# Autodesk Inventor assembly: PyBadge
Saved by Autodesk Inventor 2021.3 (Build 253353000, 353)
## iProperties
Created: 2021-11
Part Number: PyBadge
Document SubType Name: Assembly
Designer: Administrator
Title: PyBadge v1
Author: Administrator
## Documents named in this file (2)
- c:\worker\convert-fusion-r08\tmp\job-1\162\output\files\9e9872d7-303c-4258-bf7a-9e680d27e2c3\3139cef1-33fa-4c08-b4f7-0bd19bf1993e.iam
- c:\worker\convert-fusion-r08\tmp\job-1\162\output\files\9e9872d7-303c-4258-bf7a-9e680d27e2c3\pyBadge rev F2 v6.iam
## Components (1 placed, 1 different names)
1. pyBadge rev F2 v6:1 [sub-assembly]
